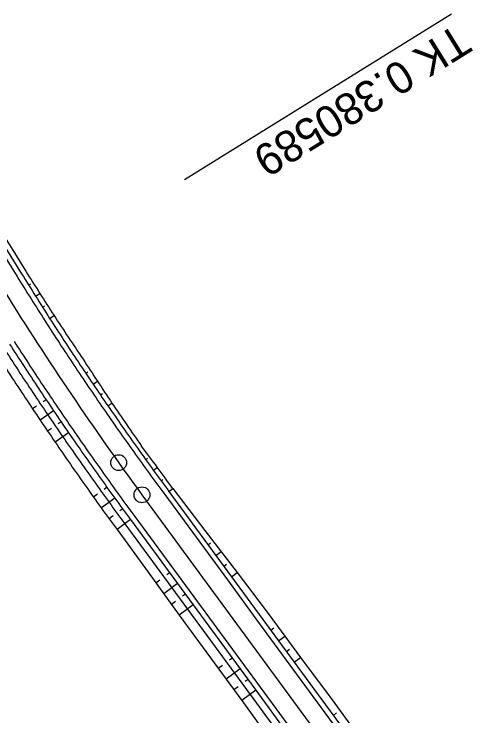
# Model space of a CAD drawing. Extents: x -481656 to -478728, y -1113199 to -1110710.
# Drawn here: x -480676.8 to -480633.4, y -1112872.3 to -1112806 of the extents above; entities that cross this region are included whole.
import ezdxf

# ---------------------------------------------------------------- set-up
doc = ezdxf.new("R2010")
doc.units = 0
for name, color, linetype in [('C13_HATCH_SLOPE_L', 7, 'Continuous'), ('C13_HATCH_SLOPE_R', 7, 'Continuous'), ('C13_HECTOMETRY', 7, 'Continuous'), ('C13_HLBODY', 7, 'Continuous'), ('C13_HRANA_TELESO', 7, 'Continuous'), ('C13_KORUNA', 7, 'Continuous'), ('C13_OSA', 7, 'Continuous'), ('C13_PRIKOP', 7, 'Continuous'), ('C13_VOZOVKA', 7, 'Continuous'), ('C13_ZPEVKRAJ', 7, 'Continuous')]:
    doc.layers.add(name, color=color, linetype=linetype)

msp = doc.modelspace()

# ---------------------------------------------------------------- linework, layer by layer
at = {"layer": 'C13_HATCH_SLOPE_L'}
for p, q in [((-480675.438, -1112831.557), (-480675.238, -1112831.432)), ((-480675.038, -1112831.308), (-480675.038, -1112831.308)), ((-480674.778, -1112832.608), (-480674.374, -1112832.353)), ((-480674.115, -1112833.656), (-480673.911, -1112833.526)), ((-480673.706, -1112833.397), (-480673.706, -1112833.397)), ((-480673.447, -1112834.702), (-480673.034, -1112834.437)), ((-480670.041, -1112839.887), (-480669.827, -1112839.743)), ((-480669.613, -1112839.599), (-480669.613, -1112839.599)), ((-480669.348, -1112840.915), (-480668.935, -1112840.635)), ((-480668.649, -1112841.941), (-480668.45, -1112841.805)), ((-480668.252, -1112841.669), (-480668.252, -1112841.669)), ((-480667.947, -1112842.963), (-480667.565, -1112842.7)), ((-480664.371, -1112848.032), (-480664.2, -1112847.909)), ((-480664.03, -1112847.786), (-480664.03, -1112847.786)), ((-480663.643, -1112849.036), (-480663.299, -1112848.786)), ((-480662.911, -1112850.038), (-480662.738, -1112849.911)), ((-480662.565, -1112849.784), (-480662.565, -1112849.784)), ((-480662.171, -1112851.046), (-480661.821, -1112850.789)), ((-480658.473, -1112856.084), (-480658.24, -1112855.912)), ((-480658.006, -1112855.741), (-480658.006, -1112855.741)), ((-480657.733, -1112857.092), (-480657.242, -1112856.731)), ((-480656.479, -1112857.721), (-480656.479, -1112857.721)), ((-480656.994, -1112858.099), (-480656.736, -1112857.91)), ((-480656.254, -1112859.107), (-480655.715, -1112858.711)), ((-480652.556, -1112864.145), (-480652.257, -1112863.926)), ((-480651.958, -1112863.706), (-480651.958, -1112863.706)), ((-480651.816, -1112865.153), (-480651.216, -1112864.712)), ((-480651.077, -1112866.161), (-480650.776, -1112865.94)), ((-480650.474, -1112865.719), (-480650.474, -1112865.719)), ((-480650.337, -1112867.169), (-480649.732, -1112866.725)), ((-480646.639, -1112872.207), (-480646.331, -1112871.981)), ((-480646.023, -1112871.755), (-480646.023, -1112871.755))]:
    msp.add_line(p, q, dxfattribs=at)
at = {"layer": 'C13_HATCH_SLOPE_R'}
for p, q in [((-480673.777, -1112842.396), (-480674.054, -1112842.582)), ((-480674.692, -1112843.011), (-480675.055, -1112843.254)), ((-480673.072, -1112843.44), (-480674.351, -1112844.306)), ((-480673.278, -1112845.106), (-480673.642, -1112845.355)), ((-480672.364, -1112844.481), (-480672.639, -1112844.669)), ((-480671.651, -1112845.519), (-480672.929, -1112846.401)), ((-480668.021, -1112850.664), (-480668.291, -1112850.859)), ((-480668.93, -1112851.32), (-480669.3, -1112851.587)), ((-480667.282, -1112851.684), (-480668.561, -1112852.615)), ((-480666.539, -1112852.701), (-480666.808, -1112852.898)), ((-480667.447, -1112853.368), (-480667.818, -1112853.64)), ((-480665.799, -1112853.708), (-480667.082, -1112854.65)), ((-480662.101, -1112858.747), (-480662.37, -1112858.944)), ((-480663.02, -1112859.422), (-480663.403, -1112859.702)), ((-480661.361, -1112859.754), (-480662.666, -1112860.713)), ((-480660.621, -1112860.762), (-480660.89, -1112860.96)), ((-480661.544, -1112861.44), (-480661.93, -1112861.723)), ((-480659.882, -1112861.77), (-480661.194, -1112862.733)), ((-480656.184, -1112866.808), (-480656.452, -1112867.006)), ((-480657.117, -1112867.493), (-480657.512, -1112867.783)), ((-480655.444, -1112867.816), (-480656.775, -1112868.793)), ((-480654.704, -1112868.824), (-480654.973, -1112869.021)), ((-480655.64, -1112869.51), (-480656.038, -1112869.803)), ((-480653.965, -1112869.831), (-480655.301, -1112870.813))]:
    msp.add_line(p, q, dxfattribs=at)
at = {"layer": 'C13_HECTOMETRY'}
msp.add_circle((-480666.925, -1112848.332), 0.75, dxfattribs=at)
at = {"layer": 'C13_HLBODY'}
msp.add_line((-480635.481, -1112805.957), (-480660.708, -1112821.632), dxfattribs=at)
msp.add_circle((-480664.724, -1112851.371), 0.75, dxfattribs=at)
at = {"layer": 'C13_HRANA_TELESO'}
for p, q in [((-480678.345, -1112826.011), (-480675.701, -1112830.255)), ((-480661.821, -1112850.789), (-480658.769, -1112854.751)), ((-480667.082, -1112854.65), (-480664.139, -1112858.692)), ((-480658.769, -1112854.751), (-480655.715, -1112858.711)), ((-480664.139, -1112858.692), (-480661.194, -1112862.733)), ((-480655.715, -1112858.711), (-480652.699, -1112862.7)), ((-480661.194, -1112862.733), (-480658.249, -1112866.774)), ((-480652.699, -1112862.7), (-480649.732, -1112866.725)), ((-480658.249, -1112866.774), (-480655.301, -1112870.813)), ((-480649.732, -1112866.725), (-480646.765, -1112870.749)), ((-480655.301, -1112870.813), (-480652.355, -1112874.852)), ((-480646.765, -1112870.749), (-480643.798, -1112874.774))]:
    msp.add_line(p, q, dxfattribs=at)
for centre, radius, start, end in [((-479922.472, -1112352.852), 891.778, 212.366886, 212.685556), ((-480424.277, -1112671.739), 297.238, 213.18635, 214.14131), ((-480423.024, -1112673.635), 303.787, 212.74733, 213.70226), ((-480420.584, -1112677.294), 297.252, 212.85556, 213.81059), ((-480422.254, -1112674.783), 303.794, 213.44157, 214.39651), ((-480421.236, -1112676.22), 297.31, 214.05258, 215.00756), ((-480422.209, -1112674.815), 303.813, 214.38669, 215.34163), ((-480783.207, -1112936.622), 148.667, 35.26462, 37.17881), ((-480545.358, -1112763.764), 151.912, 214.84324, 216.74722)]:
    msp.add_arc(centre, radius, start, end, dxfattribs=at)
at = {"layer": 'C13_KORUNA'}
for p, q in [((-480678.734, -1112826.253), (-480676.095, -1112830.5)), ((-480662.171, -1112851.046), (-480659.213, -1112855.076)), ((-480665.799, -1112853.708), (-480662.84, -1112857.739)), ((-480659.213, -1112855.076), (-480656.254, -1112859.107)), ((-480662.84, -1112857.739), (-480659.882, -1112861.77)), ((-480656.254, -1112859.107), (-480653.296, -1112863.138)), ((-480659.882, -1112861.77), (-480656.923, -1112865.801)), ((-480653.296, -1112863.138), (-480650.337, -1112867.169)), ((-480656.923, -1112865.801), (-480653.965, -1112869.831)), ((-480650.337, -1112867.169), (-480647.378, -1112871.199)), ((-480653.965, -1112869.831), (-480651.006, -1112873.862)), ((-480647.378, -1112871.199), (-480644.42, -1112875.23))]:
    msp.add_line(p, q, dxfattribs=at)
for centre, radius, start, end in [((-479919.133, -1112356.26), 893.25, 212.067306, 212.385897), ((-480422.881, -1112673.855), 297.75, 212.69777, 213.6527), ((-480422.881, -1112673.855), 302.25, 212.69777, 213.6527), ((-480422.881, -1112673.855), 297.75, 213.6527, 214.60763), ((-480422.881, -1112673.855), 302.25, 213.6527, 214.60763), ((-480422.881, -1112673.855), 297.75, 214.60763, 215.56256), ((-480422.881, -1112673.855), 302.25, 214.60763, 215.56256), ((-480543.224, -1112761.518), 148.875, 215.05399, 216.96753), ((-480545.046, -1112762.837), 151.125, 215.05656, 216.96295)]:
    msp.add_arc(centre, radius, start, end, dxfattribs=at)
at = {"layer": 'C13_OSA'}
msp.add_line((-480664.724, -1112851.371), (-480634.276, -1112892.852), dxfattribs=at)
msp.add_arc((-480422.88, -1112673.855), 300, 211.85533, 216.27914, dxfattribs=at)
at = {"layer": 'C13_PRIKOP'}
for p, q in [((-480666.336, -1112854.103), (-480663.378, -1112858.133)), ((-480663.378, -1112858.133), (-480660.419, -1112862.164)), ((-480660.419, -1112862.164), (-480657.46, -1112866.195)), ((-480657.46, -1112866.195), (-480654.502, -1112870.226)), ((-480654.502, -1112870.226), (-480651.543, -1112874.256))]:
    msp.add_line(p, q, dxfattribs=at)
for centre, radius, start, end in [((-480422.881, -1112673.855), 302.916, 212.69777, 213.6527), ((-480422.881, -1112673.855), 302.916, 213.6527, 214.60763), ((-480422.881, -1112673.855), 302.916, 214.60763, 215.56256), ((-480545.316, -1112763.033), 151.458, 215.05694, 216.96228)]:
    msp.add_arc(centre, radius, start, end, dxfattribs=at)
at = {"layer": 'C13_VOZOVKA'}
for p, q in [((-480679.159, -1112826.517), (-480676.52, -1112830.764)), ((-480662.574, -1112851.342), (-480659.616, -1112855.372)), ((-480665.396, -1112853.413), (-480662.437, -1112857.443)), ((-480659.616, -1112855.372), (-480656.657, -1112859.403)), ((-480662.437, -1112857.443), (-480659.479, -1112861.474)), ((-480656.657, -1112859.403), (-480653.699, -1112863.434)), ((-480659.479, -1112861.474), (-480656.52, -1112865.505)), ((-480653.699, -1112863.434), (-480650.74, -1112867.464)), ((-480656.52, -1112865.505), (-480653.562, -1112869.535)), ((-480650.74, -1112867.464), (-480647.781, -1112871.495)), ((-480653.562, -1112869.535), (-480650.603, -1112873.566)), ((-480647.781, -1112871.495), (-480644.823, -1112875.526))]:
    msp.add_line(p, q, dxfattribs=at)
for centre, radius, start, end in [((-479918.287, -1112355.726), 894.75, 212.067411, 212.385939), ((-480422.881, -1112673.855), 298.25, 212.69777, 213.6527), ((-480422.881, -1112673.855), 301.75, 212.69777, 213.6527), ((-480422.881, -1112673.855), 298.25, 213.6527, 214.60763), ((-480422.881, -1112673.855), 301.75, 213.6527, 214.60763), ((-480422.881, -1112673.855), 298.25, 214.60763, 215.56256), ((-480422.881, -1112673.855), 301.75, 214.60763, 215.56256), ((-480543.426, -1112761.664), 149.125, 215.05428, 216.96701), ((-480544.844, -1112762.691), 150.875, 215.05628, 216.96345)]:
    msp.add_arc(centre, radius, start, end, dxfattribs=at)
at = {"layer": 'C13_ZPEVKRAJ'}
for p, q in [((-480679.159, -1112826.517), (-480676.52, -1112830.764)), ((-480662.574, -1112851.342), (-480659.616, -1112855.372)), ((-480665.396, -1112853.413), (-480662.437, -1112857.443)), ((-480659.616, -1112855.372), (-480656.657, -1112859.403)), ((-480662.437, -1112857.443), (-480659.479, -1112861.474)), ((-480656.657, -1112859.403), (-480653.699, -1112863.434)), ((-480659.479, -1112861.474), (-480656.52, -1112865.505)), ((-480653.699, -1112863.434), (-480650.74, -1112867.464)), ((-480656.52, -1112865.505), (-480653.562, -1112869.535)), ((-480650.74, -1112867.464), (-480647.781, -1112871.495)), ((-480653.562, -1112869.535), (-480650.603, -1112873.566)), ((-480647.781, -1112871.495), (-480644.823, -1112875.526))]:
    msp.add_line(p, q, dxfattribs=at)
for centre, radius, start, end in [((-479918.287, -1112355.726), 894.75, 212.067411, 212.385939), ((-480422.881, -1112673.855), 298.25, 212.69777, 213.6527), ((-480422.881, -1112673.855), 301.75, 212.69777, 213.6527), ((-480422.881, -1112673.855), 298.25, 213.6527, 214.60763), ((-480422.881, -1112673.855), 301.75, 213.6527, 214.60763), ((-480422.881, -1112673.855), 298.25, 214.60763, 215.56256), ((-480422.881, -1112673.855), 301.75, 214.60763, 215.56256), ((-480543.426, -1112761.664), 149.125, 215.05428, 216.96701), ((-480544.844, -1112762.691), 150.875, 215.05628, 216.96345)]:
    msp.add_arc(centre, radius, start, end, dxfattribs=at)

# ---------------------------------------------------------------- texts
at = {"layer": 'C13_HLBODY'}
msp.add_text('TK 0.380589', height=2.999, rotation=211.85534, dxfattribs=at).set_placement((-480634.953, -1112806.806))

doc.saveas('drawing.dxf')
